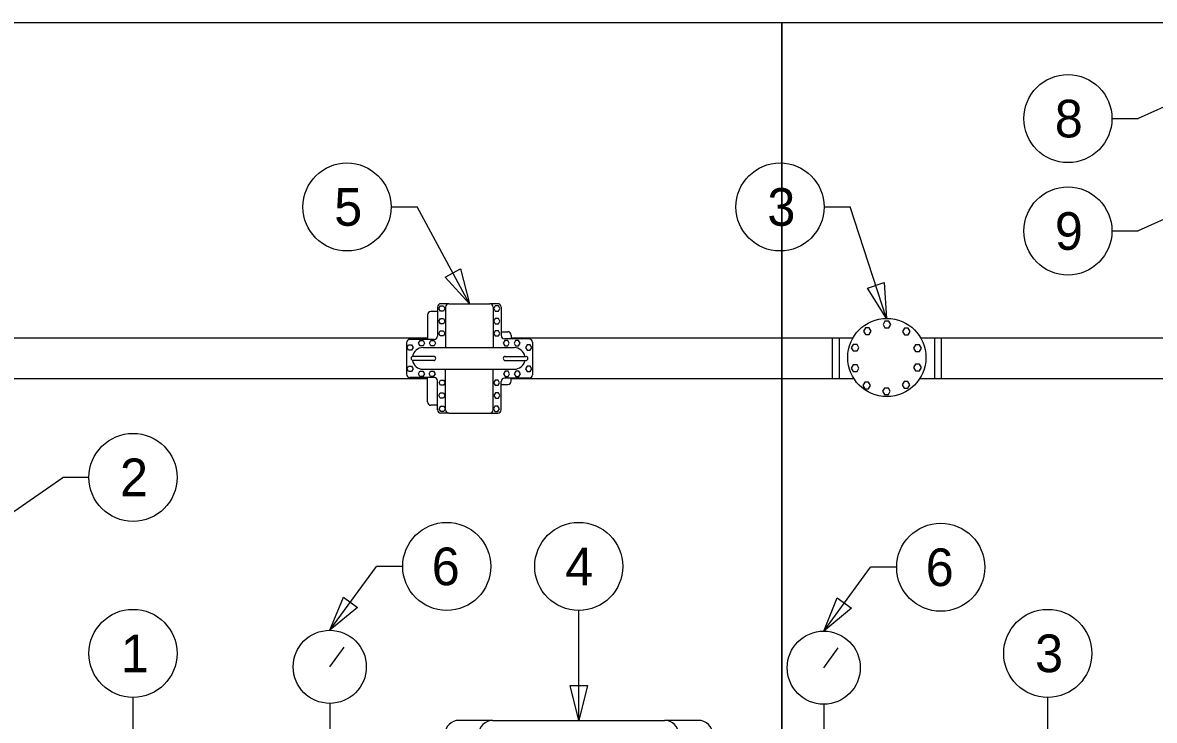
# Model space of a CAD drawing. Extents: x 10442.9 to 10533.9, y 10030 to 10079.1.
# Drawn here: x 10473.91 to 10495.58, y 10065.76 to 10079.12 of the extents above; entities that cross this region are included whole.
import ezdxf

# ---------------------------------------------------------------- set-up
doc = ezdxf.new("R2010")
doc.units = 0
for name, color, linetype in [('G-ANNO-NPLT', 7, 'Continuous'), ('G-ANNO-SYMB', 7, 'Continuous'), ('G-DETL-LINE', 7, 'Continuous')]:
    doc.layers.add(name, color=color, linetype=linetype)

msp = doc.modelspace()

# ---------------------------------------------------------------- linework, layer by layer
at = {"layer": 'G-ANNO-NPLT'}
for points in [[(10442.947, 10029.978), (10442.947, 10079.12), (10488.447, 10079.12), (10488.447, 10029.978)], [(10488.447, 10029.978), (10488.447, 10079.12), (10533.947, 10079.12), (10533.947, 10029.978)]]:
    msp.add_lwpolyline(points, close=True, dxfattribs=at)
at = {"layer": 'G-ANNO-SYMB'}
for centre in [(10493.924, 10077.283), (10480.12, 10075.59), (10488.411, 10075.59), (10493.924, 10075.13), (10476.023, 10070.411), (10482.03, 10068.706), (10484.557, 10068.706), (10491.488, 10068.69), (10476.023, 10067.041), (10493.538, 10067.041)]:
    msp.add_circle(centre, 0.843, dxfattribs=at)
at = {"layer": 'G-DETL-LINE'}
for p, q in [((10496.856, 10078.002), (10495.267, 10077.283)), ((10494.767, 10077.283), (10495.267, 10077.283)), ((10496.856, 10075.849), (10495.267, 10075.13)), ((10480.962, 10075.59), (10481.462, 10075.59)), ((10482.463, 10073.738), (10481.462, 10075.59)), ((10489.253, 10075.59), (10489.753, 10075.59)), ((10490.453, 10073.456), (10489.753, 10075.59)), ((10494.767, 10075.13), (10495.267, 10075.13)), ((10481.854, 10073.673), (10481.854, 10073.118)), ((10482.073, 10073.738), (10481.919, 10073.738)), ((10482.009, 10073.673), (10482.009, 10072.896)), ((10482.073, 10073.738), (10482.853, 10073.738)), ((10483.007, 10073.738), (10482.853, 10073.738)), ((10482.917, 10073.673), (10482.917, 10072.89)), ((10483.071, 10073.673), (10483.071, 10073.13)), ((10481.661, 10073.523), (10481.661, 10073.054)), ((10481.854, 10073.587), (10481.725, 10073.587)), ((10481.661, 10073.079), (10473.222, 10073.079)), ((10481.79, 10073.054), (10481.324, 10073.054)), ((10483.071, 10073.201), (10483.201, 10073.201)), ((10483.605, 10073.065), (10483.135, 10073.065)), ((10483.265, 10073.137), (10483.265, 10073.065)), ((10489.806, 10073.079), (10483.265, 10073.079)), ((10489.412, 10073.079), (10489.412, 10072.299)), ((10489.541, 10073.079), (10489.541, 10072.299)), ((10501.153, 10073.079), (10491.106, 10073.079)), ((10491.366, 10073.079), (10491.366, 10072.299)), ((10491.496, 10073.079), (10491.496, 10072.299)), ((10481.26, 10072.99), (10481.26, 10072.388)), ((10481.576, 10072.896), (10483.323, 10072.896)), ((10483.669, 10073.001), (10483.669, 10072.377)), ((10481.78, 10072.729), (10481.387, 10072.729)), ((10481.78, 10072.649), (10481.387, 10072.649)), ((10483.151, 10072.729), (10483.543, 10072.729)), ((10483.151, 10072.649), (10483.543, 10072.649)), ((10481.576, 10072.482), (10483.323, 10072.482)), ((10482.009, 10071.705), (10482.009, 10072.482)), ((10482.917, 10071.705), (10482.917, 10072.476)), ((10481.661, 10072.299), (10473.222, 10072.299)), ((10481.79, 10072.324), (10481.324, 10072.324)), ((10481.661, 10071.856), (10481.661, 10072.324)), ((10481.854, 10071.705), (10481.854, 10072.26)), ((10483.071, 10071.705), (10483.071, 10072.249)), ((10483.083, 10072.189), (10483.201, 10072.189)), ((10483.605, 10072.313), (10483.135, 10072.313)), ((10483.265, 10072.253), (10483.265, 10072.313)), ((10489.829, 10072.299), (10483.265, 10072.299)), ((10504.132, 10072.299), (10491.084, 10072.299)), ((10481.854, 10071.792), (10481.725, 10071.792)), ((10482.073, 10071.641), (10481.919, 10071.641)), ((10482.073, 10071.641), (10482.853, 10071.641)), ((10482.853, 10071.641), (10483.007, 10071.641)), ((10472.768, 10069.09), (10474.68, 10070.411)), ((10475.18, 10070.411), (10474.68, 10070.411)), ((10479.79, 10067.483), (10480.687, 10068.706)), ((10481.187, 10068.706), (10480.687, 10068.706)), ((10489.248, 10067.467), (10490.145, 10068.69)), ((10490.645, 10068.69), (10490.145, 10068.69)), ((10484.557, 10065.758), (10484.557, 10067.864)), ((10479.79, 10066.783), (10480.066, 10067.163)), ((10489.248, 10066.767), (10489.524, 10067.147)), ((10476.023, 10063.425), (10476.023, 10066.199)), ((10479.79, 10066.083), (10479.79, 10065.579)), ((10493.538, 10063.263), (10493.538, 10066.199)), ((10489.248, 10066.067), (10489.248, 10065.563)), ((10482.914, 10065.758), (10482.265, 10065.758)), ((10482.914, 10065.758), (10486.201, 10065.758)), ((10486.85, 10065.758), (10486.201, 10065.758))]:
    msp.add_line(p, q, dxfattribs=at)
for points in [[(10482.293, 10074.403), (10482.463, 10073.738), (10481.999, 10074.245)], [(10490.404, 10074.142), (10490.453, 10073.456), (10490.087, 10074.038)], [(10481.879, 10073.646), (10481.908, 10073.696), (10481.966, 10073.696), (10481.994, 10073.646), (10481.966, 10073.596), (10481.908, 10073.596)], [(10483.047, 10073.646), (10483.018, 10073.696), (10482.96, 10073.696), (10482.931, 10073.646), (10482.96, 10073.596), (10483.018, 10073.596)], [(10481.879, 10073.405), (10481.908, 10073.456), (10481.966, 10073.456), (10481.994, 10073.405), (10481.966, 10073.355), (10481.908, 10073.355)], [(10483.047, 10073.405), (10483.018, 10073.456), (10482.96, 10073.456), (10482.931, 10073.405), (10482.96, 10073.355), (10483.018, 10073.355)], [(10490.157, 10073.213), (10490.12, 10073.277), (10490.047, 10073.277), (10490.01, 10073.213), (10490.047, 10073.149), (10490.12, 10073.149)], [(10490.532, 10073.338), (10490.495, 10073.402), (10490.421, 10073.402), (10490.384, 10073.338), (10490.421, 10073.274), (10490.495, 10073.274)], [(10490.904, 10073.206), (10490.867, 10073.269), (10490.793, 10073.269), (10490.757, 10073.206), (10490.793, 10073.142), (10490.867, 10073.142)], [(10481.491, 10072.98), (10481.52, 10073.03), (10481.578, 10073.03), (10481.606, 10072.98), (10481.578, 10072.93), (10481.52, 10072.93)], [(10481.699, 10072.98), (10481.728, 10073.03), (10481.786, 10073.03), (10481.814, 10072.98), (10481.786, 10072.93), (10481.728, 10072.93)], [(10481.878, 10073.17), (10481.907, 10073.22), (10481.965, 10073.22), (10481.994, 10073.17), (10481.965, 10073.12), (10481.907, 10073.12)], [(10483.047, 10073.17), (10483.018, 10073.22), (10482.96, 10073.22), (10482.931, 10073.17), (10482.96, 10073.12), (10483.018, 10073.12)], [(10483.227, 10072.98), (10483.198, 10073.03), (10483.14, 10073.03), (10483.111, 10072.98), (10483.14, 10072.93), (10483.198, 10072.93)], [(10483.435, 10072.98), (10483.406, 10073.03), (10483.348, 10073.03), (10483.319, 10072.98), (10483.348, 10072.93), (10483.406, 10072.93)], [(10481.27, 10072.899), (10481.299, 10072.949), (10481.357, 10072.949), (10481.386, 10072.899), (10481.357, 10072.849), (10481.299, 10072.849)], [(10483.656, 10072.899), (10483.627, 10072.949), (10483.569, 10072.949), (10483.54, 10072.899), (10483.569, 10072.849), (10483.627, 10072.849)], [(10489.922, 10072.895), (10489.886, 10072.959), (10489.812, 10072.959), (10489.775, 10072.895), (10489.812, 10072.832), (10489.886, 10072.832)], [(10491.117, 10072.886), (10491.08, 10072.95), (10491.006, 10072.95), (10490.969, 10072.886), (10491.006, 10072.822), (10491.08, 10072.822)], [(10481.27, 10072.491), (10481.299, 10072.541), (10481.357, 10072.541), (10481.386, 10072.491), (10481.357, 10072.441), (10481.299, 10072.441)], [(10481.486, 10072.396), (10481.515, 10072.446), (10481.573, 10072.446), (10481.602, 10072.396), (10481.573, 10072.346), (10481.515, 10072.346)], [(10481.692, 10072.396), (10481.721, 10072.446), (10481.779, 10072.446), (10481.808, 10072.396), (10481.779, 10072.346), (10481.721, 10072.346)], [(10483.233, 10072.396), (10483.204, 10072.446), (10483.146, 10072.446), (10483.117, 10072.396), (10483.146, 10072.346), (10483.204, 10072.346)], [(10483.439, 10072.396), (10483.41, 10072.446), (10483.352, 10072.446), (10483.323, 10072.396), (10483.352, 10072.346), (10483.41, 10072.346)], [(10483.656, 10072.491), (10483.627, 10072.541), (10483.569, 10072.541), (10483.54, 10072.491), (10483.569, 10072.441), (10483.627, 10072.441)], [(10489.922, 10072.5), (10489.886, 10072.564), (10489.812, 10072.564), (10489.775, 10072.5), (10489.812, 10072.437), (10489.886, 10072.437)], [(10491.117, 10072.513), (10491.08, 10072.577), (10491.006, 10072.577), (10490.969, 10072.513), (10491.006, 10072.449), (10491.08, 10072.449)], [(10481.884, 10072.225), (10481.913, 10072.275), (10481.971, 10072.275), (10482, 10072.225), (10481.971, 10072.175), (10481.913, 10072.175)], [(10483.042, 10072.225), (10483.013, 10072.275), (10482.955, 10072.275), (10482.926, 10072.225), (10482.955, 10072.175), (10483.013, 10072.175)], [(10490.144, 10072.174), (10490.108, 10072.238), (10490.034, 10072.238), (10489.997, 10072.174), (10490.034, 10072.11), (10490.108, 10072.11)], [(10490.897, 10072.185), (10490.86, 10072.249), (10490.787, 10072.249), (10490.75, 10072.185), (10490.787, 10072.121), (10490.86, 10072.121)], [(10481.878, 10071.98), (10481.907, 10072.03), (10481.965, 10072.03), (10481.993, 10071.98), (10481.965, 10071.93), (10481.907, 10071.93)], [(10483.048, 10071.98), (10483.019, 10072.03), (10482.961, 10072.03), (10482.932, 10071.98), (10482.961, 10071.93), (10483.019, 10071.93)], [(10490.523, 10072.06), (10490.486, 10072.123), (10490.412, 10072.123), (10490.375, 10072.06), (10490.412, 10071.996), (10490.486, 10071.996)], [(10481.886, 10071.723), (10481.915, 10071.774), (10481.973, 10071.774), (10482.002, 10071.723), (10481.973, 10071.673), (10481.915, 10071.673)], [(10483.04, 10071.723), (10483.011, 10071.774), (10482.953, 10071.774), (10482.924, 10071.723), (10482.953, 10071.673), (10483.011, 10071.673)], [(10480.319, 10067.922), (10479.79, 10067.483), (10480.05, 10068.119)], [(10489.777, 10067.906), (10489.248, 10067.467), (10489.508, 10068.103)], [(10484.724, 10066.425), (10484.557, 10065.758), (10484.391, 10066.425)]]:
    msp.add_lwpolyline(points, close=True, dxfattribs=at)
for centre, radius in [((10490.456, 10072.708), 0.749), ((10479.79, 10066.783), 0.7), ((10489.248, 10066.767), 0.7)]:
    msp.add_circle(centre, radius, dxfattribs=at)
for centre, radius, start, end in [((10481.919, 10073.673), 0.0641, 90, 180), ((10482.073, 10073.673), 0.0641, 90, 180), ((10482.853, 10073.673), 0.0641, 0, 90), ((10483.007, 10073.673), 0.0641, 0, 90), ((10481.725, 10073.523), 0.0641, 90, 180), ((10481.324, 10072.99), 0.0641, 90, 180), ((10481.79, 10073.118), 0.0641, 270, 0), ((10483.135, 10073.13), 0.0641, 180, 270), ((10483.201, 10073.137), 0.0641, 0, 90), ((10483.605, 10073.001), 0.0641, 0, 90), ((10481.576, 10072.689), 0.207, 90, 169.7691), ((10483.323, 10072.689), 0.207, 11.1065, 90), ((10481.387, 10072.689), 0.0399, 90, 270), ((10481.576, 10072.689), 0.207, 190.2309, 270), ((10481.78, 10072.689), 0.0399, 270, 90), ((10483.151, 10072.689), 0.0399, 90, 270), ((10483.323, 10072.689), 0.207, 270, 348.8935), ((10483.543, 10072.689), 0.0399, 270, 90), ((10481.324, 10072.388), 0.0641, 180, 270), ((10483.605, 10072.377), 0.0641, 270, 0), ((10481.79, 10072.26), 0.0641, 0, 90), ((10483.135, 10072.249), 0.0641, 90, 180), ((10483.201, 10072.253), 0.0641, 270, 0), ((10481.725, 10071.856), 0.0641, 180, 270), ((10481.919, 10071.705), 0.0641, 180, 270), ((10482.073, 10071.705), 0.0641, 180, 270), ((10482.853, 10071.705), 0.0641, 270, 0), ((10483.007, 10071.705), 0.0641, 270, 0), ((10482.265, 10065.488), 0.27, 90, 180), ((10482.914, 10065.488), 0.27, 90, 180), ((10486.201, 10065.488), 0.27, 0, 90), ((10486.85, 10065.488), 0.27, 0, 90)]:
    msp.add_arc(centre, radius, start, end, dxfattribs=at)

# ---------------------------------------------------------------- texts
at = {"layer": 'G-ANNO-SYMB'}
for s, p in [('8', (10493.672, 10076.922)), ('5', (10479.875, 10075.23)), ('3', (10488.169, 10075.23)), ('9', (10493.674, 10074.769)), ('2', (10475.774, 10070.051)), ('6', (10481.743, 10068.346)), ('4', (10484.299, 10068.346)), ('6', (10491.201, 10068.33)), ('1', (10475.792, 10066.681)), ('3', (10493.295, 10066.681))]:
    msp.add_text(s, height=0.721, dxfattribs=at).set_placement(p)

doc.saveas('drawing.dxf')
